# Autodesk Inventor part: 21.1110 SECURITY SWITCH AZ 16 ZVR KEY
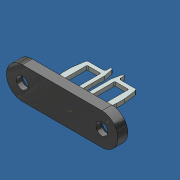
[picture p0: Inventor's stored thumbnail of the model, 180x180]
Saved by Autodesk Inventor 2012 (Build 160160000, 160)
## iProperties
Created: 2007-05
Part Number: 21.1110 SECURITY SWITCH AZ 16 ZVR KEY
Material: Steel
Document SubType Name: Modeling
Designer: Andy Moles
Density: 7.85 g/cm^3
Author: Andy Moles
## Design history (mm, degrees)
feature "Base1"
body "Solid1"
